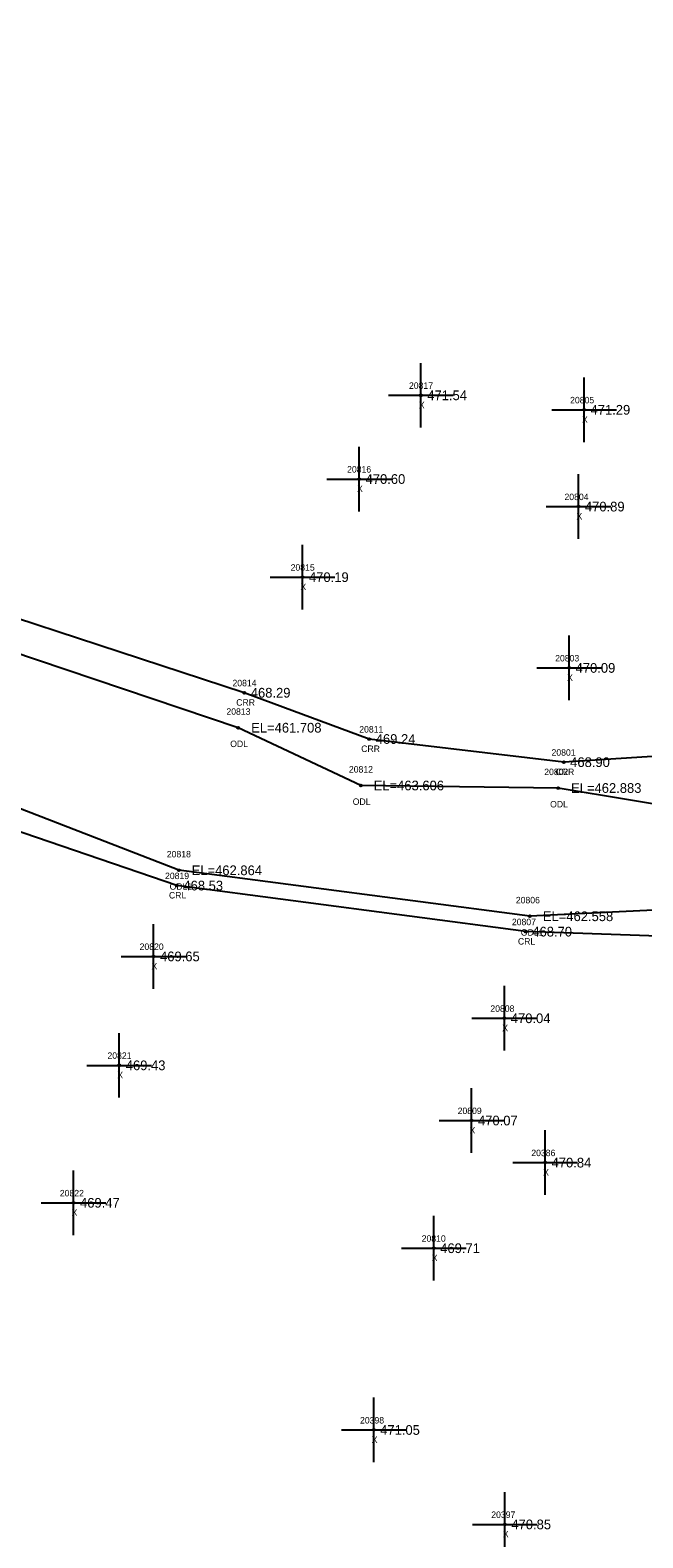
# Model space of a CAD drawing. Extents: x 1741010 to 1742139, y 749382 to 750625.
# Drawn here: x 1741414.3 to 1741509, y 750041.3 to 750274.5 of the extents above; entities that cross this region are included whole.
import ezdxf

# ---------------------------------------------------------------- set-up
doc = ezdxf.new("R2010")
doc.units = 0
for name, color, linetype in [('RD_EX_H2O', 7, 'Continuous'), ('RD_EX_H2O_txCode', 7, 'Continuous'), ('RD_EX_Misc', 7, 'Continuous'), ('RD_EX_Misc_txCode', 7, 'Continuous'), ('RD_EX_TX_H2O_ELEV', 7, 'Continuous'), ('RD_EX_TX_Misc_ELEV', 7, 'Continuous'), ('RD_SMD_Locator', 7, 'Continuous')]:
    doc.layers.add(name, color=color, linetype=linetype)

msp = doc.modelspace()

# ---------------------------------------------------------------- linework, layer by layer
at = {"layer": 'RD_EX_H2O'}
for points in [[(1741531.4, 750163.48), (1741496.74, 750161.28), (1741466.68, 750164.86), (1741447.36, 750172.02), (1741386.3, 750192.01), (1741353.76, 750217.14), (1741329.62, 750224.53), (1741303.91, 750221.92), (1741291.61, 750196.83), (1741282.64, 750163.36), (1741273.67, 750156.83), (1741266.54, 750162.04), (1741226.59, 750163.86), (1741212.64, 750167.03), (1741192.26, 750172.18), (1741170.42, 750180.69), (1741154.09, 750191.77), (1741121.46, 750224.58), (1741091.69, 750251.93), (1741067.74, 750274.52)], [(1741529.44, 750151.69), (1741495.88, 750157.28), (1741465.36, 750157.67), (1741446.42, 750166.61), (1741384.48, 750187.47), (1741350.45, 750210.87), (1741329.18, 750218), (1741305.86, 750217.64), (1741298.92, 750196.11), (1741302.53, 750181.39), (1741301.05, 750174.92), (1741291.08, 750166.14), (1741279.91, 750156.54), (1741273.82, 750151.82), (1741263.7, 750152.66), (1741226.75, 750162.85), (1741212.53, 750164.38), (1741190.98, 750170.64), (1741169.63, 750179.08), (1741152.49, 750189.88), (1741119.79, 750222.83), (1741091.32, 750250.11), (1741061.1, 750271.73)], [(1741521.3, 750138.92), (1741491.52, 750137.44), (1741437.22, 750144.55), (1741376.8, 750167.97), (1741340.99, 750191.87), (1741329.47, 750196.35), (1741318.56, 750196.32), (1741315.14, 750190.31), (1741314.27, 750183.41), (1741309.93, 750180.68), (1741308.62, 750179.31), (1741310.53, 750161.19), (1741313.05, 750147.55), (1741307.9, 750138.2), (1741297.98, 750128.4), (1741291.92, 750127.29), (1741274.87, 750127.82), (1741267.79, 750139.08), (1741257.86, 750136.37), (1741230.74, 750145.22)], [(1741577.19, 750059.87), (1741574.31, 750069.19), (1741563.25, 750082.19), (1741560.12, 750095.32), (1741559.96, 750109.5), (1741556.5, 750127.16), (1741554.14, 750131.7), (1741543.79, 750140.45), (1741537.22, 750131.72), (1741525.85, 750130.27), (1741518.7, 750134.1), (1741490.89, 750135.06), (1741436.94, 750142.19), (1741375.71, 750163.12), (1741339.37, 750188.79), (1741331.64, 750190.2), (1741328.64, 750186.11), (1741320.24, 750158.32), (1741318.27, 750146.83), (1741309.48, 750135.97), (1741304.66, 750127.91)]]:
    msp.add_lwpolyline(points, dxfattribs=at)
at = {"layer": 'RD_EX_Misc'}
for p, q in [((1741474.65, 750213.03), (1741474.65, 750223.03)), ((1741499.89, 750210.79), (1741499.89, 750220.79)), ((1741469.65, 750218.03), (1741479.65, 750218.03)), ((1741494.89, 750215.79), (1741504.89, 750215.79)), ((1741465.11, 750200.08), (1741465.11, 750210.08)), ((1741460.11, 750205.08), (1741470.11, 750205.08)), ((1741499.02, 750195.82), (1741499.02, 750205.82)), ((1741494.02, 750200.82), (1741504.02, 750200.82)), ((1741456.36, 750184.9), (1741456.36, 750194.9)), ((1741451.36, 750189.9), (1741461.36, 750189.9)), ((1741497.58, 750170.86), (1741497.58, 750180.86)), ((1741492.58, 750175.86), (1741502.58, 750175.86)), ((1741433.33, 750126.23), (1741433.33, 750136.23)), ((1741428.33, 750131.23), (1741438.33, 750131.23)), ((1741487.56, 750116.66), (1741487.56, 750126.66)), ((1741482.56, 750121.66), (1741492.56, 750121.66)), ((1741428.03, 750109.38), (1741428.03, 750119.38)), ((1741423.03, 750114.38), (1741433.03, 750114.38)), ((1741482.49, 750100.84), (1741482.49, 750110.84)), ((1741477.49, 750105.84), (1741487.49, 750105.84)), ((1741493.87, 750094.33), (1741493.87, 750104.33)), ((1741420.96, 750088.11), (1741420.96, 750098.11)), ((1741488.87, 750099.33), (1741498.87, 750099.33)), ((1741415.96, 750093.11), (1741425.96, 750093.11)), ((1741476.65, 750081.09), (1741476.65, 750091.09)), ((1741471.65, 750086.09), (1741481.65, 750086.09)), ((1741467.37, 750052.97), (1741467.37, 750062.97)), ((1741462.37, 750057.97), (1741472.37, 750057.97)), ((1741487.65, 750038.36), (1741487.65, 750048.36)), ((1741482.65, 750043.36), (1741492.65, 750043.36))]:
    msp.add_line(p, q, dxfattribs=at)
at = {"layer": 'RD_SMD_Locator'}
for centre in [(1741474.65, 750218.03), (1741499.89, 750215.79), (1741465.11, 750205.08), (1741499.02, 750200.82), (1741456.36, 750189.9), (1741497.58, 750175.86), (1741447.36, 750172.02), (1741446.42, 750166.61), (1741466.68, 750164.86), (1741496.74, 750161.28), (1741465.36, 750157.67), (1741495.88, 750157.28), (1741437.22, 750144.55), (1741436.94, 750142.19), (1741491.52, 750137.44), (1741490.89, 750135.06), (1741433.33, 750131.23), (1741487.56, 750121.66), (1741428.03, 750114.38), (1741482.49, 750105.84), (1741493.87, 750099.33), (1741420.96, 750093.11), (1741476.65, 750086.09), (1741467.37, 750057.97), (1741487.65, 750043.36)]:
    msp.add_circle(centre, 0.15, dxfattribs=at)

# ---------------------------------------------------------------- texts
at = {"layer": 'RD_EX_H2O_txCode'}
for s, p in [('20814', (1741445.53, 750173.02)), ('CRR', (1741446.11, 750170.02)), ('20813', (1741444.59, 750168.61)), ('20811', (1741465.13, 750165.86)), ('ODL', (1741445.18, 750163.61)), ('CRR', (1741465.43, 750162.86)), ('20801', (1741494.86, 750162.28)), ('20812', (1741463.53, 750159.67)), ('20802', (1741493.73, 750159.28)), ('CRR', (1741495.48, 750159.28)), ('ODL', (1741464.12, 750154.67)), ('ODL', (1741494.64, 750154.28)), ('20818', (1741435.38, 750146.55)), ('20819', (1741435.1, 750143.19)), ('ODL1', (1741435.81, 750141.55)), ('CRL', (1741435.71, 750140.19)), ('20806', (1741489.34, 750139.44)), ('20807', (1741488.73, 750136.06)), ('ODL1', (1741490.11, 750134.44)), ('CRL', (1741489.66, 750133.06))]:
    msp.add_text(s, height=1, dxfattribs=at).set_placement(p)
at = {"layer": 'RD_EX_Misc_txCode'}
for s, p in [('20817', (1741472.82, 750219.03)), ('X', (1741474.34, 750216.03)), ('20805', (1741497.73, 750216.79)), ('X', (1741499.57, 750213.79)), ('20816', (1741463.25, 750206.08)), ('X', (1741464.79, 750203.08)), ('20804', (1741496.86, 750201.82)), ('X', (1741498.71, 750198.82)), ('20815', (1741454.52, 750190.9)), ('X', (1741456.04, 750187.9)), ('20803', (1741495.42, 750176.86)), ('X', (1741497.26, 750173.86)), ('20820', (1741431.17, 750132.23)), ('X', (1741433.01, 750129.23)), ('20808', (1741485.4, 750122.66)), ('X', (1741487.24, 750119.66)), ('20821', (1741426.2, 750115.38)), ('X', (1741427.72, 750112.38)), ('20809', (1741480.34, 750106.84)), ('X', (1741482.18, 750103.84)), ('20386', (1741491.73, 750100.33)), ('X', (1741493.56, 750097.33)), ('20822', (1741418.84, 750094.11)), ('X', (1741420.65, 750091.11)), ('20810', (1741474.78, 750087.09)), ('X', (1741476.34, 750084.09)), ('20398', (1741465.25, 750058.97)), ('X', (1741467.05, 750055.97)), ('20397', (1741485.54, 750044.36)), ('X', (1741487.34, 750041.36))]:
    msp.add_text(s, height=1, dxfattribs=at).set_placement(p)
at = {"layer": 'RD_EX_TX_H2O_ELEV'}
for s, p in [('468.29', (1741448.36, 750171.27)), ('EL=461.708', (1741448.42, 750165.86)), ('469.24', (1741467.68, 750164.11)), ('468.90', (1741497.74, 750160.53)), ('EL=463.606', (1741467.36, 750156.92)), ('EL=462.883', (1741497.88, 750156.53)), ('EL=462.864', (1741439.22, 750143.8)), ('468.53', (1741437.94, 750141.44)), ('EL=462.558', (1741493.52, 750136.69)), ('468.70', (1741491.89, 750134.31))]:
    msp.add_text(s, height=1.5, dxfattribs=at).set_placement(p)
at = {"layer": 'RD_EX_TX_Misc_ELEV'}
for s, p in [('471.54', (1741475.65, 750217.28)), ('471.29', (1741500.89, 750215.04)), ('470.60', (1741466.11, 750204.33)), ('470.89', (1741500.02, 750200.07)), ('470.19', (1741457.36, 750189.15)), ('470.09', (1741498.58, 750175.11)), ('469.65', (1741434.33, 750130.48)), ('470.04', (1741488.56, 750120.91)), ('469.43', (1741429.03, 750113.63)), ('470.07', (1741483.49, 750105.09)), ('470.84', (1741494.87, 750098.58)), ('469.47', (1741421.96, 750092.36)), ('469.71', (1741477.65, 750085.34)), ('471.05', (1741468.37, 750057.22)), ('470.85', (1741488.65, 750042.61))]:
    msp.add_text(s, height=1.5, dxfattribs=at).set_placement(p)

doc.saveas('drawing.dxf')
